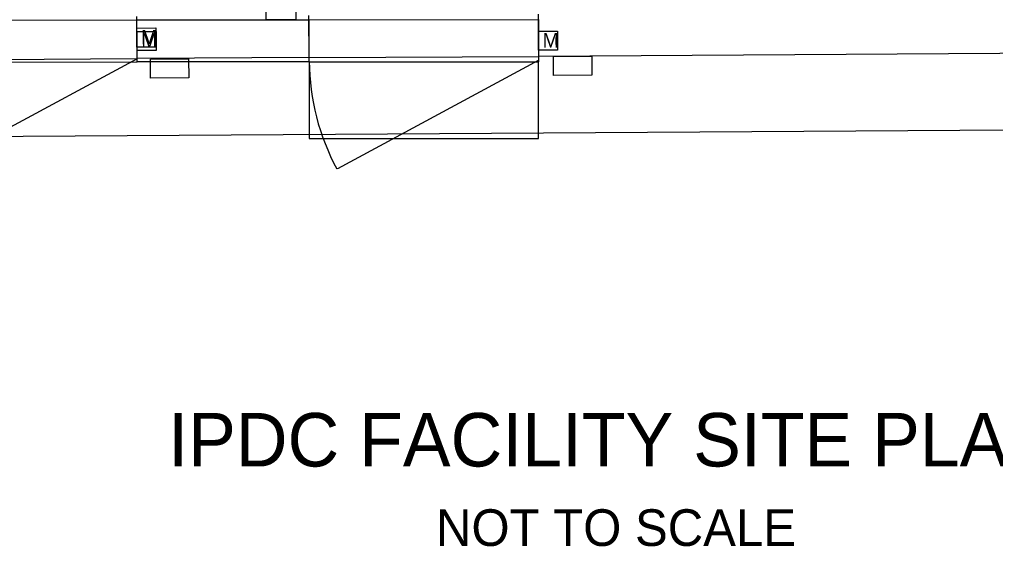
# Model space of a CAD drawing. Extents: x -2.6 to 16.3, y -2.7 to 7.5.
# Drawn here: x 3.72 to 10.11, y -2.66 to 0.79 of the extents above; entities that cross this region are included whole.
import ezdxf

# ---------------------------------------------------------------- set-up
doc = ezdxf.new("R2010")
doc.units = 0
for name, color, linetype in [('HS_Concrete_Object', 7, 'Continuous'), ('HS_Dimensions_and_Text', 7, 'Continuous'), ('HS_Electrical_Conduit', 7, 'Continuous'), ('HS_Electrical_Devices', 7, 'Continuous'), ('HS_Pattern_and_Hatching-ILTollway', 7, 'Continuous')]:
    doc.layers.add(name, color=color, linetype=linetype)

msp = doc.modelspace()

# ---------------------------------------------------------------- linework, layer by layer
at = {"layer": 'HS_Concrete_Object'}
for p, q in [((4.4915, 0.5316), (4.4898, 0.8062)), ((5.6165, 0.538), (5.6148, 0.8125)), ((0.9916, 0.5084), (4.4915, 0.5316)), ((4.4915, 0.5307), (2.9519, -0.3012)), ((5.6185, 0.5382), (7.1165, 0.5454)), ((7.1184, 0.5219), (5.8017, -0.1896))]:
    msp.add_line(p, q, dxfattribs=at)
msp.add_lwpolyline([(15.9556, 7.1018), (-0.0446, 6.9998), (0, 0), (16.0002, 0.1019)], close=True, dxfattribs=at)
for points in [[(15.4928, 1.2531), (15.497, 0.5987), (7.1165, 0.5454)], [(7.1147, 0.823), (7.1165, 0.5454)], [(5.6165, 0.5382), (4.4915, 0.5316)]]:
    msp.add_lwpolyline(points, dxfattribs=at)
msp.add_arc((7.1151, 0.5211), 1.4967, 180.36505, 208.3848, dxfattribs=at)
at = {"layer": 'HS_Dimensions_and_Text'}
msp.add_lwpolyline([(5.3351, 0.9804), (5.5304, 0.9806), (5.5306, 0.7853), (5.3353, 0.7851)], close=True, dxfattribs=at)
at = {"layer": 'HS_Electrical_Conduit'}
for points in [[(4.579, 0.5286), (4.829, 0.5302), (4.8298, 0.4052), (4.5798, 0.4036)], [(7.2151, 0.5454), (7.4651, 0.547), (7.4659, 0.422), (7.2159, 0.4204)]]:
    msp.add_lwpolyline(points, close=True, dxfattribs=at)
at = {"layer": 'HS_Electrical_Devices'}
for p, q in [((0.9914, 0.7811), (4.4914, 0.7843)), ((4.4917, 0.5098), (4.4914, 0.7843)), ((5.6164, 0.7854), (7.1164, 0.7868)), ((5.6167, 0.5102), (5.6164, 0.7845)), ((0.9917, 0.5057), (4.4917, 0.5098)), ((5.6167, 0.5102), (7.1167, 0.5092))]:
    msp.add_line(p, q, dxfattribs=at)
for points in [[(4.4914, 0.7843), (5.6164, 0.7854)], [(7.1164, 0.7868), (7.1167, 0.5092)], [(5.6167, 0.5102), (4.4917, 0.5098)], [(5.6167, 0.5102), (5.6171, 0.0078), (7.1171, 0.0092), (7.1167, 0.5092)]]:
    msp.add_lwpolyline(points, dxfattribs=at)
for points in [[(4.4915, 0.7095), (4.6165, 0.7097), (4.6166, 0.5847), (4.4916, 0.5845)], [(7.1165, 0.7105), (7.2415, 0.7106), (7.2416, 0.5856), (7.1166, 0.5855)]]:
    msp.add_lwpolyline(points, close=True, dxfattribs=at)
at = {"layer": 'HS_Pattern_and_Hatching-ILTollway'}
msp.add_lwpolyline([(4.4903, 0.7314), (4.6153, 0.7322), (4.6161, 0.6072), (4.4911, 0.6064)], close=True, dxfattribs=at)

# ---------------------------------------------------------------- texts
at = {"layer": 'HS_Dimensions_and_Text'}
msp.add_text('M', height=0.0944, rotation=0.36505, dxfattribs=at).set_placement((4.5187, 0.6244))
for s, height, p in [('IPDC FACILITY SITE PLAN', 0.35, (4.6957, -2.1373)), ('NOT TO SCALE ', 0.24, (6.4468, -2.6573))]:
    msp.add_text(s, height=height, dxfattribs=at).set_placement(p)
at = {"layer": 'HS_Electrical_Devices'}
for p in [(4.5193, 0.6024), (7.1441, 0.6038)]:
    msp.add_text('M', height=0.0944, rotation=0.05234, dxfattribs=at).set_placement(p)

doc.saveas('drawing.dxf')
